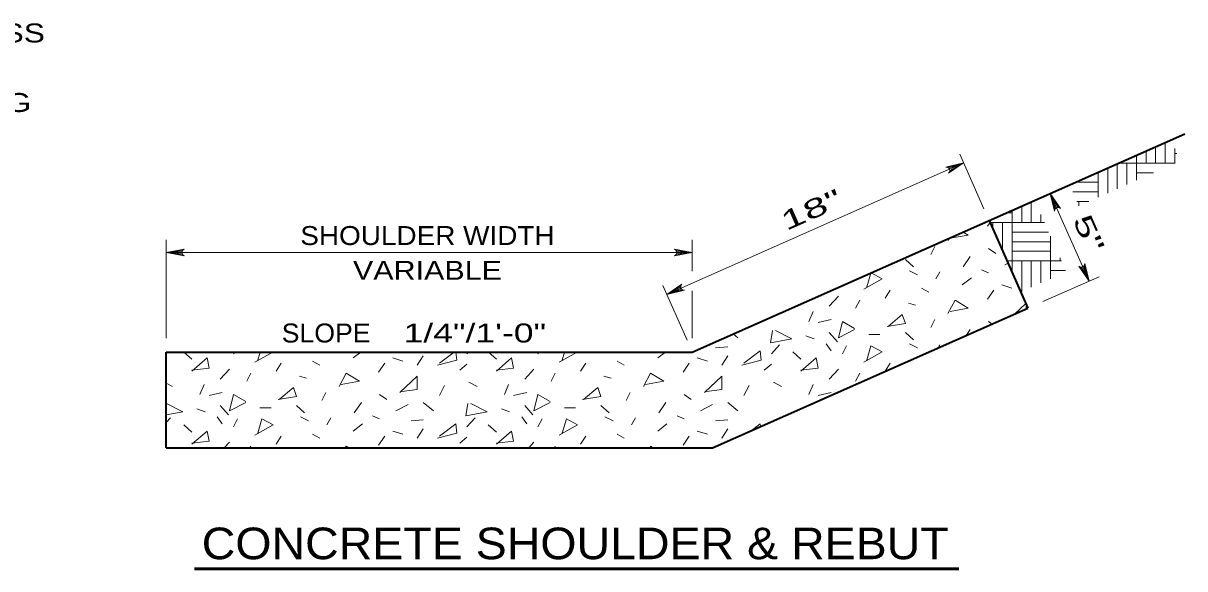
# Model space of a CAD drawing. Extents: x -10 to 104, y -162 to -1.
# Drawn here: x 35.7 to 96.3, y -29.7 to -1.2 of the extents above; entities that cross this region are included whole.
import ezdxf
from ezdxf.enums import TextEntityAlignment as Align

# ---------------------------------------------------------------- set-up
doc = ezdxf.new("R2010")
doc.units = 0
doc.header["$LTSCALE"] = 0.4
for name, color, linetype, lineweight in [('1', 7, 'Continuous', 35), ('10', 7, 'Continuous', 13), ('12', 7, 'Continuous', 53), ('6', 7, 'Continuous', 13)]:
    doc.layers.add(name, color=color, linetype=linetype, lineweight=lineweight)
doc.layers.add('13', color=7, linetype='Continuous')

msp = doc.modelspace()

# ---------------------------------------------------------------- linework, layer by layer
at = {"layer": '1'}
for p, q in [((70.6144, -18.3471), (96.3083, -6.9611)), ((86.1034, -11.4833), (88.1291, -16.0546)), ((71.6726, -23.3471), (88.1291, -16.0546)), ((43.1726, -23.3471), (43.1726, -18.3471)), ((43.1726, -18.3471), (70.6144, -18.3471)), ((43.1726, -23.3471), (71.6726, -23.3471))]:
    msp.add_line(p, q, dxfattribs=at)
at = {"layer": '1', "lineweight": 13}
for p, q in [((95.7894, -8.4924), (95.7894, -8.4824)), ((91.7471, -8.9824), (91.7894, -8.9824)), ((91.2894, -10.4865), (91.2894, -10.4824)), ((75.1372, -21.8118), (75.1652, -21.7802))]:
    msp.add_line(p, q, dxfattribs=at)
at = {"layer": '10'}
for p, q in [((84.7704, -8.4752), (69.2814, -15.339)), ((85.8294, -10.8648), (84.5643, -8.01)), ((91.3168, -14.642), (89.2911, -10.0708)), ((43.1726, -17.6242), (43.1726, -12.4951)), ((70.6144, -14.1182), (70.6144, -12.4951)), ((70.6144, -13.1443), (43.1726, -13.1443)), ((88.8946, -15.7154), (91.8341, -14.4127)), ((70.3403, -17.7286), (69.0752, -14.8739)), ((70.6144, -17.6242), (70.6144, -15.157))]:
    msp.add_line(p, q, dxfattribs=at)
for points in [[(84.7704, -8.4752), (83.9891, -9.0126), (84.0346, -8.938), (84.0431, -8.8658), (84.0276, -8.8043), (83.9925, -8.7515), (83.9333, -8.7094), (83.8475, -8.693), (84.7704, -8.4752), (83.9333, -8.7094), (83.9925, -8.7515), (84.7704, -8.4752), (84.0276, -8.8043), (84.0431, -8.8658), (84.7704, -8.4752), (84.0346, -8.938)], [(89.2911, -10.0708), (89.8284, -10.8521), (89.7539, -10.8066), (89.6817, -10.7981), (89.6202, -10.8136), (89.5674, -10.8487), (89.5253, -10.9079), (89.5089, -10.9937), (89.2911, -10.0708), (89.5253, -10.9079), (89.5674, -10.8487), (89.2911, -10.0708), (89.6202, -10.8136), (89.6817, -10.7981), (89.2911, -10.0708), (89.7539, -10.8066)], [(43.1726, -13.1443), (44.1047, -12.9696), (44.0328, -13.0193), (43.9958, -13.0818), (43.9851, -13.1443), (43.9958, -13.2068), (44.0328, -13.2693), (44.1047, -13.3191), (43.1726, -13.1443), (44.0328, -13.2693), (43.9958, -13.2068), (43.1726, -13.1443), (43.9851, -13.1443), (43.9958, -13.0818), (43.1726, -13.1443), (44.0328, -13.0193)], [(70.6144, -13.1443), (69.6823, -13.3191), (69.7541, -13.2693), (69.7911, -13.2068), (69.8019, -13.1443), (69.7911, -13.0818), (69.7541, -13.0193), (69.6823, -12.9696), (70.6144, -13.1443), (69.7541, -13.0193), (69.7911, -13.0818), (70.6144, -13.1443), (69.8019, -13.1443), (69.7911, -13.2068), (70.6144, -13.1443), (69.7541, -13.2693)], [(91.3168, -14.642), (90.7794, -13.8607), (90.854, -13.9062), (90.9261, -13.9147), (90.9876, -13.8992), (91.0404, -13.8641), (91.0825, -13.8049), (91.0989, -13.7191), (91.3168, -14.642), (91.0825, -13.8049), (91.0404, -13.8641), (91.3168, -14.642), (90.9876, -13.8992), (90.9261, -13.9147), (91.3168, -14.642), (90.854, -13.9062)], [(69.2814, -15.339), (70.0627, -14.8016), (70.0172, -14.8762), (70.0087, -14.9483), (70.0242, -15.0098), (70.0593, -15.0626), (70.1185, -15.1047), (70.2043, -15.1211), (69.2814, -15.339), (70.1185, -15.1047), (70.0593, -15.0626), (69.2814, -15.339), (70.0242, -15.0098), (70.0087, -14.9483), (69.2814, -15.339), (70.0172, -14.8762)]]:
    msp.add_lwpolyline(points, dxfattribs=at)
at = {"layer": '12'}
msp.add_line((44.6512, -29.6614), (84.512, -29.6614), dxfattribs=at)
at = {"layer": '6'}
for p, q in [((94.2894, -8.4824), (94.2894, -7.8558)), ((94.7894, -8.4824), (94.7894, -7.6342)), ((95.2894, -8.4824), (95.2894, -7.4127)), ((95.7894, -8.4824), (95.7894, -7.7263)), ((92.8754, -8.4824), (93.7894, -8.4824)), ((93.2894, -9.6002), (93.2894, -8.4824)), ((93.7894, -8.4824), (93.7894, -8.0774)), ((95.7894, -7.9824), (95.9028, -7.9824)), ((91.7894, -10.265), (91.7894, -8.9636)), ((92.2894, -10.0434), (92.2894, -8.7421)), ((92.7894, -9.8218), (92.7894, -8.5205)), ((93.7894, -8.9824), (94.6836, -8.9824)), ((90.6188, -9.4824), (91.7894, -9.4824)), ((90.4637, -9.9824), (91.7894, -9.9824)), ((87.7994, -11.5852), (87.7994, -10.7317)), ((88.2994, -11.5852), (88.2994, -10.5102)), ((90.6853, -10.4824), (91.2987, -10.4824)), ((90.7894, -10.7081), (90.7894, -10.4824)), ((87.0017, -11.0852), (87.2994, -11.0852)), ((87.2994, -11.5852), (87.2994, -10.9533)), ((88.7994, -11.5852), (88.7994, -11.1661)), ((86.1472, -11.582), (86.0203, -11.7724)), ((86.1486, -11.5852), (87.2994, -11.5852)), ((86.2994, -11.9256), (86.2994, -11.5852)), ((86.7994, -13.0539), (86.7994, -11.5852)), ((87.2994, -13.5852), (87.2994, -11.5852)), ((87.2994, -11.5852), (88.9852, -11.5852)), ((87.2994, -12.0852), (89.2067, -12.0852)), ((83.9552, -12.5137), (84.0107, -12.4107)), ((87.2994, -12.5852), (89.2994, -12.5852)), ((89.2994, -13.5852), (89.2994, -12.2944)), ((83.055, -13.2551), (83.2668, -12.8315)), ((86.0732, -12.9374), (86.4439, -13.2021)), ((87.2994, -13.0852), (89.2994, -13.0852)), ((81.7312, -13.5198), (82.1548, -13.8905)), ((85.1201, -13.361), (84.7494, -13.8905)), ((87.0864, -13.7016), (86.9204, -13.7846)), ((87.0349, -13.5852), (87.2994, -13.5852)), ((87.2994, -14.1822), (87.2994, -13.5852)), ((87.2994, -13.5852), (89.2994, -13.5852)), ((87.7994, -15.1808), (87.7994, -13.5852)), ((88.2994, -14.9592), (88.2994, -13.5852)), ((88.7994, -14.7377), (88.7994, -13.5852)), ((89.2994, -14.5161), (89.2994, -13.5852)), ((89.2994, -13.5852), (89.8714, -13.5852)), ((89.7994, -13.5852), (89.7994, -13.4227)), ((79.9275, -14.2201), (79.719, -14.9495)), ((81.943, -14.1023), (82.3666, -14.3141)), ((83.3197, -14.5259), (83.5316, -14.1552)), ((85.173, -14.473), (84.6965, -14.8436)), ((85.7026, -14.0494), (86.0732, -14.2082)), ((87.2565, -14.0852), (87.2994, -14.0852)), ((89.2994, -14.0852), (90.093, -14.0852)), ((80.6722, -15.532), (80.9369, -15.1084)), ((82.5784, -15.0025), (82.9491, -15.2143)), ((86.338, -15.1084), (86.0203, -15.5849)), ((86.7616, -14.8436), (87.2911, -15.0025)), ((78.2364, -15.4261), (77.7599, -15.9556)), ((79.3484, -15.6379), (79.1366, -16.0615)), ((75.2258, -16.3036), (75.2711, -16.3262)), ((76.9126, -16.2204), (76.7008, -16.7499)), ((81.8901, -15.7967), (82.2607, -15.9026)), ((88.0201, -15.8084), (87.4287, -16.3649)), ((88.0324, -16.0974), (88.0324, -15.8363)), ((77.8658, -16.644), (77.1774, -16.8028)), ((83.055, -17.0676), (83.2668, -16.644)), ((86.0732, -16.7499), (86.2596, -16.883)), ((72.7492, -17.4011), (72.9942, -17.5971)), ((76.542, -17.4912), (76.9656, -17.65)), ((77.7599, -17.3323), (78.1835, -17.8089)), ((79.825, -17.4382), (80.4074, -17.4382)), ((81.7312, -17.3323), (82.1548, -17.703)), ((85.1201, -17.1735), (84.9024, -17.4844)), ((71.8293, -18.1266), (72.4647, -18.0736)), ((74.7416, -18.4443), (75.1652, -17.9677)), ((77.601, -17.9148), (77.8658, -18.2855)), ((78.66, -18.0207), (78.4482, -18.4443)), ((81.943, -17.9148), (82.3666, -18.1266)), ((83.4365, -18.134), (83.5316, -17.9677)), ((44.0927, -18.3471), (44.5064, -18.7091)), ((46.726, -18.3471), (46.6774, -18.4443)), ((47.7894, -18.8679), (48.7268, -18.3471)), ((48.0668, -18.3471), (47.9482, -18.762)), ((53.3229, -18.3471), (52.9256, -18.6561)), ((54.9907, -18.6561), (55.5203, -18.815)), ((56.2616, -19.0268), (56.5793, -18.5502)), ((58.1916, -18.3471), (57.4265, -18.9209)), ((58.8562, -18.4443), (58.9426, -18.3471)), ((59.9781, -18.3471), (60.3918, -18.7091)), ((62.6114, -18.3471), (62.5628, -18.4443)), ((63.6748, -18.8679), (64.6123, -18.3471)), ((63.9522, -18.3471), (63.8336, -18.762)), ((69.2084, -18.3471), (68.8111, -18.6561)), ((70.8762, -18.6561), (71.4057, -18.815)), ((72.147, -19.0268), (72.4647, -18.5502)), ((75.8536, -18.3384), (76.2772, -18.7091)), ((46.4656, -19.2386), (45.989, -19.7681)), ((48.9013, -19.3445), (49.1661, -18.9209)), ((50.8076, -18.815), (51.1782, -19.0268)), ((54.5671, -18.9209), (54.2494, -19.3974)), ((58.4855, -19.2915), (58.8562, -18.9738)), ((62.351, -19.2386), (61.8744, -19.7681)), ((64.7867, -19.3445), (65.0515, -18.9209)), ((66.693, -18.815), (67.0637, -19.0268)), ((70.4526, -18.9209), (70.1349, -19.3974)), ((74.371, -19.2915), (74.7416, -18.9738)), ((78.2364, -19.2386), (77.7599, -19.7681)), ((80.6722, -19.3445), (80.9369, -18.9209)), ((43.1726, -19.9749), (43.5003, -20.1387)), ((47.5776, -19.4504), (47.3657, -19.874)), ((50.1192, -19.6092), (50.4899, -19.7151)), ((58.9621, -19.927), (59.3857, -20.1387)), ((63.463, -19.4504), (63.2512, -19.874)), ((66.0046, -19.6092), (66.3753, -19.7151)), ((74.8475, -19.927), (75.2711, -20.1387)), ((79.3484, -19.4504), (79.1366, -19.874)), ((45.1418, -20.0329), (44.93, -20.5624)), ((46.0949, -20.4565), (45.4066, -20.6153)), ((51.2842, -20.8801), (51.496, -20.4565)), ((54.3024, -20.5624), (54.673, -20.8271)), ((57.4265, -20.6153), (57.6913, -20.0858)), ((61.0272, -20.0329), (60.8154, -20.5624)), ((61.9804, -20.4565), (61.292, -20.6153)), ((67.1696, -20.8801), (67.3814, -20.4565)), ((70.1878, -20.5624), (70.5585, -20.8271)), ((73.3119, -20.6153), (73.5767, -20.0858)), ((76.9126, -20.0329), (76.7008, -20.5624)), ((77.8658, -20.4565), (77.1774, -20.6153)), ((45.989, -21.1448), (46.4126, -21.6214)), ((49.9604, -21.1448), (50.384, -21.5155)), ((53.3493, -20.986), (52.9786, -21.5155)), ((55.785, -21.0919), (55.1496, -21.4096)), ((56.5793, -20.986), (57.1088, -21.4096)), ((61.8744, -21.1448), (62.2981, -21.6214)), ((65.8458, -21.1448), (66.2694, -21.5155)), ((69.2347, -20.986), (68.864, -21.5155)), ((71.6704, -21.0919), (71.035, -21.4096)), ((72.4647, -20.986), (72.9942, -21.4096)), ((43.1726, -22.0298), (43.3944, -21.7802)), ((44.7711, -21.3037), (45.1947, -21.4625)), ((45.8302, -21.7273), (46.0949, -22.098)), ((48.0541, -21.2507), (48.6366, -21.2507)), ((50.1722, -21.7273), (50.5958, -21.9391)), ((51.5489, -22.1509), (51.7607, -21.7802)), ((53.9317, -21.6744), (54.3024, -21.8332)), ((58.8562, -22.2568), (59.2798, -21.7802)), ((60.6566, -21.3037), (61.0802, -21.4625)), ((61.7156, -21.7273), (61.9804, -22.098)), ((63.9395, -21.2507), (64.522, -21.2507)), ((66.0576, -21.7273), (66.4812, -21.9391)), ((67.4343, -22.1509), (67.6461, -21.7802)), ((69.8171, -21.6744), (70.1878, -21.8332)), ((44.0828, -22.1509), (44.5064, -22.5216)), ((46.8892, -21.8332), (46.6774, -22.2568)), ((53.4022, -22.098), (52.9256, -22.4686)), ((55.9439, -21.9391), (56.5793, -21.8861)), ((56.2616, -22.8393), (56.5793, -22.3627)), ((59.9682, -22.1509), (60.3918, -22.5216)), ((62.7746, -21.8332), (62.5628, -22.2568)), ((69.2876, -22.098), (68.8111, -22.4686)), ((71.8293, -21.9391), (72.4647, -21.8861)), ((72.147, -22.8393), (72.4647, -22.3627)), ((48.9013, -23.157), (49.1661, -22.7334)), ((50.8076, -22.6275), (51.1782, -22.8393)), ((54.5671, -22.7334), (54.2494, -23.2099)), ((54.9907, -22.4686), (55.5203, -22.6275)), ((58.4855, -23.104), (58.8562, -22.7863)), ((64.7867, -23.157), (65.0515, -22.7334)), ((66.693, -22.6275), (67.0637, -22.8393)), ((70.4526, -22.7334), (70.1349, -23.2099)), ((70.8762, -22.4686), (71.4057, -22.6275)), ((46.4656, -23.0511), (46.1992, -23.3471)), ((47.5776, -23.2629), (47.5355, -23.3471)), ((62.351, -23.0511), (62.0846, -23.3471)), ((63.463, -23.2629), (63.4209, -23.3471))]:
    msp.add_line(p, q, dxfattribs=at)
for points in [[(93.7894, -9.3787), (93.7894, -8.4824), (95.7894, -8.4824), (95.8119, -8.4824)], [(84.7468, -12.0845), (85.0142, -12.249), (84.0611, -12.4079)], [(79.5602, -15.0554), (80.5133, -14.5259), (79.9414, -14.2139)], [(83.9552, -16.3262), (84.3258, -15.6379), (85.0142, -16.0615), (84.0611, -16.2204)], [(79.0836, -17.1735), (78.2364, -17.5971), (78.4482, -16.7499), (79.0836, -17.1205)], [(80.7781, -17.0146), (81.7312, -16.8558), (81.5724, -16.3792), (80.831, -17.0146)], [(74.7946, -17.2264), (74.6887, -17.8619), (75.8006, -17.65), (74.9534, -17.2264)], [(79.5602, -18.8679), (80.5133, -18.3384), (79.9309, -18.0207), (79.719, -18.762)], [(44.5064, -19.2915), (45.4066, -19.1856), (45.3007, -18.6561), (44.5064, -19.3445)], [(57.3206, -19.0268), (58.3267, -18.762), (58.2806, -18.3471)], [(60.3918, -19.2915), (61.292, -19.1856), (61.1861, -18.6561), (60.3918, -19.3445)], [(73.206, -19.0268), (74.2121, -18.762), (74.1592, -18.2855), (73.3119, -18.9209)], [(76.2772, -19.2915), (77.1774, -19.1856), (77.0715, -18.6561), (76.2772, -19.3445)], [(52.1843, -20.1387), (52.555, -19.4504), (53.2434, -19.874), (52.2902, -20.0329)], [(55.4673, -20.4035), (56.2616, -20.2976), (56.2616, -19.6092), (55.3614, -20.4565)], [(68.0697, -20.1387), (68.4404, -19.4504), (69.1288, -19.874), (68.1756, -20.0329)], [(71.3527, -20.4035), (72.147, -20.2976), (72.147, -19.6092), (71.2468, -20.4565)], [(47.3128, -20.986), (46.4656, -21.4096), (46.6774, -20.5624), (47.3128, -20.933)], [(49.0072, -20.8271), (49.9604, -20.6683), (49.8015, -20.1917), (49.0602, -20.8271)], [(63.1982, -20.986), (62.351, -21.4096), (62.5628, -20.5624), (63.1982, -20.933)], [(64.8927, -20.8271), (65.8458, -20.6683), (65.6869, -20.1917), (64.9456, -20.8271)], [(43.1726, -21.6258), (44.0298, -21.4625), (43.1826, -21.0389)], [(58.9092, -21.0389), (58.8032, -21.6744), (59.9152, -21.4625), (59.068, -21.0389)], [(47.7894, -22.6804), (48.7425, -22.1509), (48.16, -21.8332), (47.9482, -22.5745)], [(57.3206, -22.8393), (58.3267, -22.5745), (58.2737, -22.098), (57.4265, -22.7334)], [(63.6748, -22.6804), (64.6279, -22.1509), (64.0454, -21.8332), (63.8336, -22.5745)], [(74.1748, -22.2383), (74.1592, -22.098), (73.6794, -22.4578)], [(44.5064, -23.104), (45.4066, -22.9981), (45.3007, -22.4686), (44.5064, -23.157)], [(60.3918, -23.104), (61.292, -22.9981), (61.1861, -22.4686), (60.3918, -23.157)], [(52.5097, -23.3471), (52.555, -23.2629), (52.6918, -23.3471)], [(68.3951, -23.3471), (68.4404, -23.2629), (68.5772, -23.3471)]]:
    msp.add_lwpolyline(points, dxfattribs=at)

# ---------------------------------------------------------------- texts
at = {"layer": '12'}
for s, width, p in [('AT INTERSECTIONS, THE THICKNESS', 1.25, (6.6796, -2.1828)), ('SECTION IS SUBJECT TO EXISTING', 1.3, (6.6796, -5.8128))]:
    msp.add_text(s, height=0.99, dxfattribs=dict(at, width=width)).set_placement(p)
for s, height, width, p in [('SHOULDER WIDTH', 0.99, 1.1, (56.7968, -12.759)), ('VARIABLE', 0.99, 1.2, (56.7968, -14.574)), ('SLOPE', 0.99, 1.05, (51.5111, -17.8471)), ('CONCRETE SHOULDER & REBUT', 1.65, 1.1, (64.5068, -29.1614))]:
    msp.add_text(s, height=height, dxfattribs=dict(at, width=width)).set_placement(p, align=Align.CENTER)
at = {"layer": '13'}
for s, rotation, width, p in [('18"', 23.9, 1.7, (77.0239, -11.3611)), ('5"', 293.9, 1.65, (90.8499, -12.3543))]:
    msp.add_text(s, height=0.99, rotation=rotation, dxfattribs=dict(at, width=width)).set_placement(p, align=Align.CENTER)
at = {"layer": '13', "width": 1.4}
msp.add_text('1/4"/1\'-0"', height=0.99, dxfattribs=at).set_placement((59.2701, -17.8471), align=Align.CENTER)

doc.saveas('drawing.dxf')
